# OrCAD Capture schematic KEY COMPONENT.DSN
size A1; title: Index; note: Index
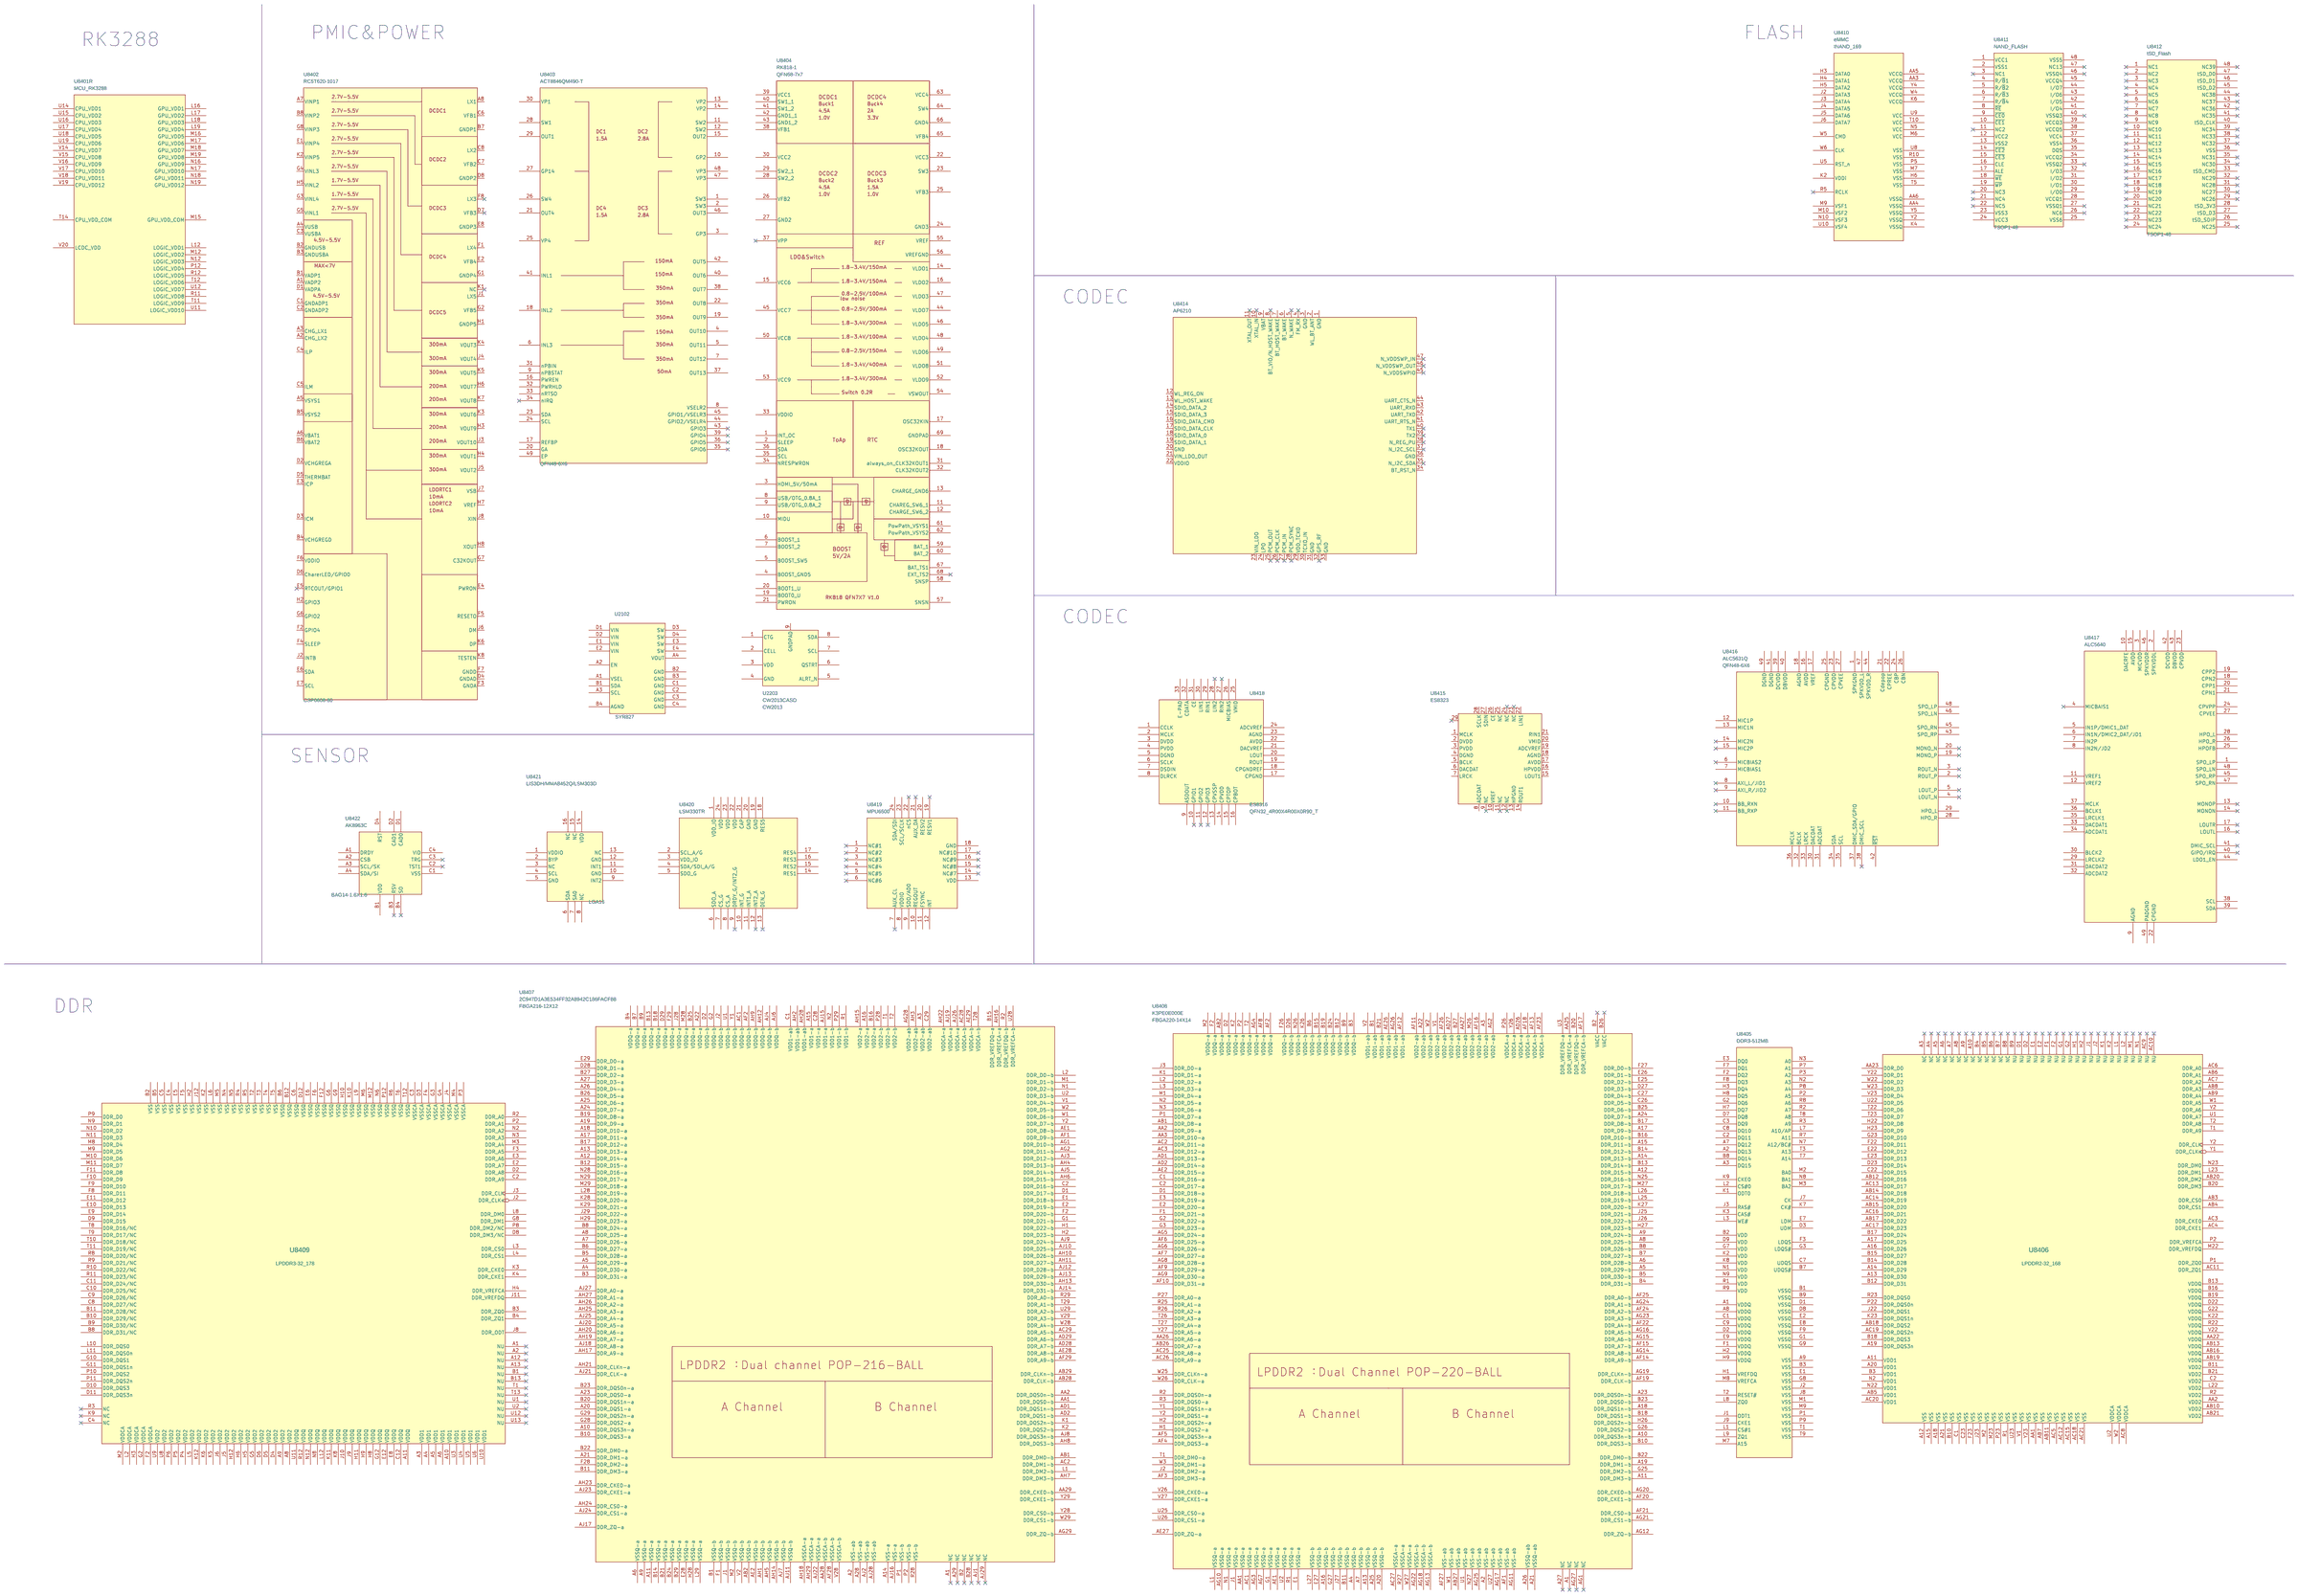
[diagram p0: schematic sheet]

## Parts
U2102  SYR827  [WLCSP-20]
U2203  CW2013CASD  [CW2013]
U8401  MCU_RK3288  [BGA636_19x19]  (section R)
U8402  RC5T620-1017  [CSP0608-80]
U8403  ACT8846QM490-T  [QFN48-6X6]
U8404  RK818-1  [QFN68-7x7]
U8405  DDR3-512MB  [FBGA96-10x14]
U8406  LPDDR2-32_168  [FBGA168-12X12]
U8407  2C947D1A3E534FF32A8942C186FACF88  [FBGA216-12X12]
U8408  K3PE0E000E  [FBGA220-14X14]
U8409  LPDDR3-32_178  [FBGA178-13X11.5]
U8410  eMMC  [INAND_169]
U8411  NAND_FLASH  [TSOP1-48]
U8412  tSD_Flash  [TSOP1-48]
U8414  AP6210  [AP6XXX]
U8415  ES8323  [WM8988]
U8416  ALC5631Q  [QFN48-6X6]
U8417  ALC5640  [763_ALC3224]
U8418  ES8316  [QFN32_4R00X4R00X0R90_T]
U8419  MPU6500  [QFN24_3R00X3R00X0R90]
U8420  LSM330TR  [LGA-24L]
U8421  LIS3DH/MMA8452Q/LSM303D  [LGA16]
U8422  AK8963C  [BAG14-1.6X1.6]

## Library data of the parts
U2102 = BB27_0
U2203 = Gage-CW2013: Fuel Gauge with Low-SOC Alert,2.5V~4.5V,TDFN8,-20 ~70℃
U8401 = MCU_RK3288
U8402 = 5T619_2
U8403 = PMIC_ACT8846: PMU IC
U8404 = PMIC_RK819_0: ROCKCHIP PMIC; Created by: JJJ; Manufacturer: Rockchip (瑞芯微); Manufacturer PN: RK819; Part Type: PMIC; Priority: A; RK PN: RK819
U8405 = DDR3_FBGA96
U8406 = LPDDR2-32_3
U8407 = K3PE0E000E_1
U8408 = K3PE0E000E_0
U8409 = LPDDR3-32bit-178PIN
U8410 = INAND_1: NAND Flash,H26M54001BKR,2.7V,3.3V,3.6V,128G,N/A,-25℃~85℃,FBGA-169P
U8411 = NANDFLASH_0: NAND Flash,2.7V,3.3V,3.6V,2G*8,N/A,-40℃~85℃,TSOP-48P; NAND FLASH: 1
U8412 = TSD_0: NAND Flash,2.7V,3.3V,3.6V,2G*8,N/A,-40℃~85℃,TSOP-48P; NAND FLASH: 1; ROW: 1
U8414 = WIFI-AP6XXX: WIFI&BT; ORCAD_LIB: MODULE; QVL: AMPAK
U8415 = wm8750_1: CODEC; Part_Type: 音频解码IC
U8416 = CODEC-ALC5631Q
U8417 = CODEC-ALC3224: CODEC
U8418 = CODEC_ES8316: Low Power Audio CODEC; Created by: JJJ; Manufacturer: Everest（顺芯）; Part Type: Codec; Priority: A
U8419 = Sensor_MPU6500
U8420 = LSM330
U8421 = MMA8452Q: G_Sensor,LIS3DH/MMA8452Q,1.95V~3.6V,LGA-16,3X3X1.0,-40°C ~ +85°C
U8422 = Sensor-AK8963C

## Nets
AGND: U8416.18(AGND)
AVDD: U8416.16(AVDD)
DGND: U8416.41(DGND) U8416.49(DGND)
GND: U8420.19(GND) U8420.20(GND)
VCC: U8410.M6(VCC) U8410.N5(VCC) U8410.T10(VCC) U8410.U9(VCC)
VCC1: U8411.1(VCC1)
VCC2: U8411.12(VCC2)
VCC3: U8411.24(VCC3)
VCC4: U8411.37(VCC4)
VCCQ: U8410.AA3(VCCQ) U8410.AA5(VCCQ) U8410.K6(VCCQ) U8410.W4(VCCQ) U8410.Y4(VCCQ)
VCCQ2: U8411.34(VCCQ2)
VCCQ3: U8411.39(VCCQ3)
VCCQ5: U8411.38(VCCQ5)
VDD: U8420.22(VDD) U8420.23(VDD) U8420.24(VDD)
VDD1: U8406.A11(VDD1) U8406.A20(VDD1) U8406.AB5(VDD1) U8406.AC20(VDD1) U8406.B3(VDD1) U8406.N2(VDD1) U8406.N22(VDD1) U8409.A3(VDD1) U8409.A4(VDD1) U8409.A5(VDD1) U8409.A6(VDD1) U8409.A10(VDD1) U8409.U3(VDD1) U8409.U4(VDD1) U8409.U5(VDD1) U8409.U6(VDD1) U8409.U10(VDD1)
VDD2: U8406.AA2(VDD2) U8406.AB10(VDD2) U8406.AB21(VDD2) U8406.B11(VDD2) U8406.B21(VDD2) U8406.C2(VDD2) U8406.L22(VDD2) U8406.R2(VDD2) U8409.A8(VDD2) U8409.A9(VDD2) U8409.D4(VDD2) U8409.D5(VDD2) U8409.D6(VDD2) U8409.G5(VDD2) U8409.H5(VDD2) U8409.H6(VDD2) U8409.H12(VDD2) U8409.J5(VDD2) U8409.J6(VDD2) U8409.K5(VDD2) U8409.K6(VDD2) U8409.K12(VDD2) U8409.L5(VDD2) U8409.P4(VDD2) U8409.P5(VDD2) U8409.P6(VDD2) U8409.U8(VDD2) U8409.U9(VDD2)
VDD_IO: U8420.1(VDD_IO) U8420.3(VDD_IO)
VDDCA: U8406.AC8(VDDCA) U8406.U2(VDDCA) U8406.W2(VDDCA) U8409.F2(VDDCA) U8409.G2(VDDCA) U8409.H3(VDDCA) U8409.L2(VDDCA) U8409.M2(VDDCA)
VDDQ: U8406.AA22(VDDQ) U8406.AB13(VDDQ) U8406.AB16(VDDQ) U8406.AB19(VDDQ) U8406.B13(VDDQ) U8406.B16(VDDQ) U8406.B19(VDDQ) U8406.D22(VDDQ) U8406.G22(VDDQ) U8406.K22(VDDQ) U8406.R22(VDDQ) U8406.V22(VDDQ) U8409.A11(VDDQ) U8409.C12(VDDQ) U8409.E8(VDDQ) U8409.E12(VDDQ) U8409.G12(VDDQ) U8409.H8(VDDQ) U8409.H9(VDDQ) U8409.H11(VDDQ) U8409.J9(VDDQ) U8409.J10(VDDQ) U8409.K8(VDDQ) U8409.K11(VDDQ) U8409.L12(VDDQ) U8409.N8(VDDQ) U8409.N12(VDDQ) U8409.R12(VDDQ) U8409.U11(VDDQ)
VSS: U8406.A12(VSS) U8406.A15(VSS) U8406.A18(VSS) U8406.A21(VSS) U8406.AA1(VSS) U8406.AB7(VSS) U8406.AB11(VSS) U8406.AC5(VSS) U8406.AC12(VSS) U8406.AC15(VSS) U8406.AC18(VSS) U8406.AC21(VSS) U8406.B10(VSS) U8406.C1(VSS) U8406.C23(VSS) U8406.F23(VSS) U8406.J23(VSS) U8406.M2(VSS) U8406.M23(VSS) U8406.P23(VSS) U8406.R1(VSS) U8406.U23(VSS) U8406.V1(VSS) U8406.Y23(VSS) U8409.B2(VSS) U8409.B5(VSS) U8409.C5(VSS) U8409.E4(VSS) U8409.E5(VSS) U8409.F5(VSS) U8409.H2(VSS) U8409.J12(VSS) U8409.K2(VSS) U8409.L6(VSS) U8409.M5(VSS) U8409.N4(VSS) U8409.N5(VSS) U8409.R4(VSS) U8409.R5(VSS) U8409.T2(VSS) U8409.T3(VSS) U8409.T4(VSS) U8409.T5(VSS) U8410.H6(VSS) U8410.M7(VSS) U8410.P5(VSS) U8410.R10(VSS) U8410.T5(VSS) U8410.U8(VSS) U8412.36(VSS)
VSS1: U8411.2(VSS1)
VSS2: U8411.13(VSS2)
VSS3: U8411.23(VSS3)
VSS4: U8411.36(VSS4)
VSS5: U8411.48(VSS5)
VSS6: U8411.25(VSS6)
VSSCA: U8409.C3(VSSCA) U8409.D3(VSSCA) U8409.F4(VSSCA) U8409.G3(VSSCA) U8409.G4(VSSCA) U8409.J4(VSSCA) U8409.M4(VSSCA) U8409.P3(VSSCA)
VSSQ: U8409.B6(VSSQ) U8409.B12(VSSQ) U8409.C6(VSSQ) U8409.D12(VSSQ) U8409.E6(VSSQ) U8409.F6(VSSQ) U8409.F12(VSSQ) U8409.G6(VSSQ) U8409.G9(VSSQ) U8409.H10(VSSQ) U8409.K10(VSSQ) U8409.L9(VSSQ) U8409.M6(VSSQ) U8409.M12(VSSQ) U8409.N6(VSSQ) U8409.P12(VSSQ) U8409.R6(VSSQ) U8409.T6(VSSQ) U8409.T12(VSSQ) U8410.AA4(VSSQ) U8410.AA6(VSSQ) U8410.K4(VSSQ) U8410.Y2(VSSQ) U8410.Y5(VSSQ)
CPGND: U8416.25(CPGND)
CPU_VDD1: U8401.U14(CPU_VDD1)
CPU_VDD2: U8401.U15(CPU_VDD2)
CPU_VDD3: U8401.U16(CPU_VDD3)
CPU_VDD4: U8401.U17(CPU_VDD4)
CPU_VDD5: U8401.U18(CPU_VDD5)
CPU_VDD6: U8401.U19(CPU_VDD6)
CPU_VDD7: U8401.V14(CPU_VDD7)
CPU_VDD8: U8401.V15(CPU_VDD8)
CPU_VDD9: U8401.V16(CPU_VDD9)
CPU_VDD10: U8401.V17(CPU_VDD10)
CPU_VDD11: U8401.V18(CPU_VDD11)
CPU_VDD12: U8401.V19(CPU_VDD12)
CPVDD: U8416.23(CPVDD)
DBVDD: U8416.40(DBVDD)
DCVDD: U8416.39(DCVDD)
DDR_VREFDQ: U8406.M22(DDR_VREFDQ) U8409.J11(DDR_VREFDQ)
GPU_VDD1: U8401.L16(GPU_VDD1)
GPU_VDD2: U8401.L17(GPU_VDD2)
GPU_VDD3: U8401.L18(GPU_VDD3)
GPU_VDD4: U8401.L19(GPU_VDD4)
GPU_VDD5: U8401.M16(GPU_VDD5)
GPU_VDD6: U8401.M17(GPU_VDD6)
GPU_VDD7: U8401.M18(GPU_VDD7)
GPU_VDD8: U8401.M19(GPU_VDD8)
GPU_VDD9: U8401.N16(GPU_VDD9)
GPU_VDD10: U8401.N17(GPU_VDD10)
GPU_VDD11: U8401.N18(GPU_VDD11)
GPU_VDD12: U8401.N19(GPU_VDD12)
LCDC_VDD: U8401.V20(LCDC_VDD)
LOGIC_VDD1: U8401.L12(LOGIC_VDD1)
LOGIC_VDD2: U8401.M12(LOGIC_VDD2)
LOGIC_VDD3: U8401.N12(LOGIC_VDD3)
LOGIC_VDD4: U8401.P12(LOGIC_VDD4)
LOGIC_VDD5: U8401.R12(LOGIC_VDD5)
LOGIC_VDD6: U8401.T12(LOGIC_VDD6)
LOGIC_VDD7: U8401.U12(LOGIC_VDD7)
LOGIC_VDD8: U8401.R11(LOGIC_VDD8)
LOGIC_VDD9: U8401.T11(LOGIC_VDD9)
LOGIC_VDD10: U8401.U11(LOGIC_VDD10)

Not connected (* = marked no-connect by the designer): U2102 A1(VSEL) A2(EN) A3(SCL) A4(VOUT) B1(SDA) B2(GND) B3(GND) B4(AGND) C1(GND) C2(GND) C3(GND) C4(GND) D1(VIN) D2(VIN) D3(SW) D4(SW) E1(VIN) E2(VIN) E3(SW) E4(SW); U2203 1(CTG) 2(CELL) 3(VDD) 4(GND) 5(ALRT_N) 6(QSTRT) 7(SCL) 8(SDA) 9(GNDPAD); U8401 M15(GPU_VDD_COM) T14(CPU_VDD_COM); U8402 A1(VADP2) A2(CHG_LX2) A3(CHG_LX1) A4(VUSB) A5(VSYS1) A6(VBAT1) A7(VINP1) A8(LX1) B1(VADP1) B2(GNDUSB) B3(GNDUSBA) B4(VCHGREGD) B5(VSYS2) B6(VBAT2) B7(GNDP1) B8(VINP2) C1(GNDADP1) C2(GNDADP2) C3(VUSBA) C4(ILP) C5(ILM) C6(VFB1) C7(VFB2) C8(LX2) D1(VADPA) D2(VCHGREGA) D3(ICM) D4(GNDAD) D5(THERMBAT) D6(CharerLED/GPIO0) D7(VFB3)* D8(GNDP2) E1(VINP4) E2(VFB4) E3(ICP) E4(PWRON) E5(RTCOUT/GPIO1)* E6(SDA) E7(SCL) E8(GNDP3) F1(LX4) F2(GPIO4) F3(GNDA) F4(SLEEP) F5(RESETO) F6(VDDIO) F7(GNDD) F8(LX3)* G1(GNDP4) G2(VFB5) G3(VINL4) G4(VINL3) G5(VINL1) G6(GPIO2) G7(C32KOUT) G8(VINP3) H1(GNDP5) H2(GPIO3) H3(VOUT9) H4(VOUT1) H5(VINL2) H6(VOUT7) H7(VREF) H8(XOUT) J1(LX5) J2(INTB) J3(VOUT10) J4(VOUT4) J5(VOUT2) J6(DM) J7(VSB) J8(XIN) K1(NC)* K2(VINP5) K3(VOUT6) K4(VOUT3) K5(VOUT5) K6(DP) K7(VOUT8) K8(TESTEN); U8403 1(SW3) 2(SW3) 3(GP3) 4(OUT10) 5(OUT11) 6(INL3) 7(OUT12) 8(VSELR2) 9(nPBSTAT) 10(GP2) 11(SW2) 12(SW2) 13(VP2) 14(VP2) 15(OUT2) 16(PWREN) 17(REFBP) 18(INL2) 19(OUT9) 20(GA) 21(OUT4) 22(OUT8) 23(SDA) 24(SCL) 25(VP4) 26(SW4) 27(GP14) 28(SW1) 29(OUT1) 30(VP1) 31(nPBIN) 32(PWRHLD) 33(nRTSO) 34(nIRQ)* 35(GPIO6)* 36(GPIO5)* 37(OUT13) 38(OUT7) 39(GPIO4)* 40(OUT6) 41(INL1) 42(OUT5) 43(GPIO3)* 44(GPIO2/VSELR4) 45(GPIO1/VSELR3) 46(OUT3) 47(VP3) 48(VP3) 49(EP); U8404 1(INT_OC) 2(SLEEP) 3(HDMI_5V/50mA) 4(BOOST_GND5) 5(BOOST_SW5) 6(BOOST_1) 7(BOOST_2) 8(USB/OTG_0.8A_1) 9(USB/OTG_0.8A_2) 10(MIDU) 11(CHAREG_SW6_1) 12(CHARGE_SW6_2) 13(CHARGE_GND6) 14(VLDO1) 15(VCC6) 16(VLDO2) 17(OSC32KIN) 18(OSC32KOUT) 19(BOOT0_U) 20(BOOT1_U) 21(PWRON) 22(VCC3) 23(SW3) 24(GND3) 25(VFB3) 26(VFB2) 27(GND2) 28(SW2_2) 29(SW2_1) 30(VCC2) 31(always_on_CLK32KOUT1) 32(CLK32KOUT2) 33(VDDIO) 34(NRESPWRON) 35(SCL) 36(SDA) 37(VPP)* 38(VFB1) 39(VCC1) 40(SW1_1) 41(SW1_2) 42(GND1_1) 43(GND1_2) 44(VLDO7) 45(VCC7) 46(VLDO5) 47(VLDO3) 48(VLDO4) 49(VLDO6) 50(VCC8) 51(VLDO8) 52(VLDO9) 53(VCC9) 54(VSWOUT) 55(VREF) 56(VREFGND) 57(SNSN) 58(SNSP) 59(BAT_1) 60(BAT_2) 61(PowPath_VSYS1) 62(PowPath_VSYS2) 63(VCC4) 64(SW4) 65(VFB4) 66(GND4) 67(BAT_TS1) 68(EXT_TS2)* 69(GNDPAD); U8405 A1(VDDQ) A2(DQ13) A3(DQ15) A7(DQ12) A8(VDDQ) A9(VSS) B1(VSSQ) B2(VDD) B3(VSS) B7(UDQS#) B8(DQ14) B9(VSSQ) C1(VDDQ) C2(DQ11) C3(DQ9) C7(UDQS) C8(DQ10) C9(VDDQ) D1(VSSQ) D2(VDDQ) D3(UDM) D7(DQ8) D8(VSSQ) D9(VDD) E1(VSS) E2(VSSQ) E3(DQ0) E7(LDM) E8(VSSQ) E9(VDDQ) F1(VDDQ) F2(DQ2) F3(LDQS) F7(DQ1) F8(DQ3) F9(VSSQ) G1(VSSQ) G2(DQ6) G3(LDQS#) G7(VDD) G8(VSS) G9(VSSQ) H1(VREFDQ) H2(VDDQ) H3(DQ4) H7(DQ7) H8(DQ5) H9(VDDQ) J1(ODT1) J2(VSS) J3(RAS#) J7(CK) J8(VSS) J9(CKE1) K1(ODT0) K2(VDD) K3(CAS#) K7(CK#) K8(VDD) K9(CKE0) L1(CS#1) L2(CS#0) L3(WE#) L7(A10/AP) L8(ZQ0) L9(ZQ1) M1(VSS) M2(BA0) M3(BA2) M7(A15) M8(VREFCA) M9(VSS) N1(VDD) N2(A3) N3(A0) N7(A12/BC#) N8(BA1) N9(VDD) P1(VSS) P2(A5) P3(A2) P7(A1) P8(A4) P9(VSS) R1(VDD) R2(A7) R3(A9) R7(A11) R8(A6) R9(VDD) T1(VSS) T2(RESET#) T3(A13) T7(A14) T8(A8) T9(VSS); U8406 A3(NC)* A4(NC)* A5(NC)* A6(NC)* A7(NC)* A8(NC)* A9(NC)* A10(NC)* A13(DDR_D30) A14(DDR_D29) A16(DDR_D26) A17(DDR_D25) A19(DDR_DQS3n) AA23(DDR_D0) AB3(DDR_CS0) AB4(DDR_CS1) AB6(DDR_A1) AB8(DDR_A3) AB9(DDR_A4) AB12(DDR_D16) AB14(DDR_D18) AB15(DDR_D20) AB17(DDR_D22) AB18(DDR_DQS2) AB20(DDR_DM2) AC3(DDR_CKE0) AC4(DDR_CKE1) AC6(DDR_A0) AC7(DDR_A2) AC9(NU)* AC10(NU)* AC11(DDR_ZQ1) AC13(DDR_D17) AC14(DDR_D19) AC16(DDR_D21) AC17(DDR_D23) AC19(DDR_DQS2n) B4(NC)* B5(NC)* B6(NC)* B7(NC)* B8(NC)* B9(NU)* B12(DDR_D31) B14(DDR_D28) B15(DDR_D27) B17(DDR_D24) B18(DDR_DQS3) B20(DDR_DM3) C22(DDR_D15) D1(NU)* D2(NU)* D23(DDR_D14) E1(NU)* E2(NU)* E22(DDR_D12) E23(DDR_D13) F1(NU)* F2(NU)* F22(DDR_D11) G1(NU)* G2(NU)* G23(DDR_D10) H1(NU)* H2(NU)* H22(DDR_D8) H23(DDR_D9) J1(NU)* J2(NU)* J22(DDR_DQS1) K1(NU)* K2(NU)* K23(DDR_DQS1n) L1(NU)* L2(NU)* L23(DDR_DM1) M1(NU)* N1(NU)* N23(DDR_DM0) P1(DDR_ZQ0) P2(DDR_VREFCA) P22(DDR_DQS0n) R23(DDR_DQS0) T1(DDR_A9) T2(DDR_A8) T22(DDR_D6) T23(DDR_D7) U1(DDR_A7) U22(DDR_D5) V2(DDR_A6) V23(DDR_D4) W1(DDR_A5) W22(DDR_D2) W23(DDR_D3) Y1(DDR_CLKn) Y2(DDR_CLK) Y22(DDR_D1); U8407 A1(NC)* A2(VSS-ab) A3(VDD2-ab) A4(DDR_D30-a) A5(DDR_D29-a) A6(VSSQ-a) A7(DDR_D26-a) A8(DDR_D25-a) A9(VSSQ-a) A10(DDR_DQS3n-a) A11(VSSQ-a) A12(DDR_D14-a) A13(DDR_D13-a) A14(VSS-a) A15(VDD1-a) A16(VDD2-a) A17(DDR_D11-a) A18(DDR_D10-a) A19(DDR_D9-a) A20(DDR_DQS1-a) A21(DDR_DM1-a) A22(VDDQ-a) A23(DDR_DQS0-a) A24(DDR_D7-a) A25(DDR_D6-a) A26(DDR_D4-a) A27(DDR_D3-a) A28(VSS-ab) A29(NC)* AA1(DDR_DQS0-b) AA2(DDR_DQS0n-b) AA28(VSSCA-b) AA29(DDR_CKE0-b) AB1(DDR_DM0-b) AB2(VSSQ-b) AB28(DDR_CLK-b) AB29(DDR_CLKn-b) AC1(VDDQ-b) AC2(DDR_DM1-b) AC28(VDDCA-b) AC29(DDR_A5-b) AD1(DDR_DQS1n-b) AD2(DDR_DQS1-b) AD28(DDR_A7-b) AD29(DDR_A6-b) AE1(DDR_D8-b) AE2(VSSQ-b) AE28(DDR_A8-b) AE29(VDDCA-b) AF1(DDR_D9-b) AF2(VDDQ-b) AF28(VSSCA-b) AF29(DDR_A9-b) AG1(DDR_D10-b) AG2(DDR_D11-b) AG28(VDD2-ab) AG29(DDR_ZQ-b) AH1(VSSQ-b) AH2(VDD1-ab) AH3(VDD2-ab) AH4(DDR_D13-b) AH5(VSSQ-b) AH6(DDR_D15-b) AH7(DDR_DM3-b) AH8(DDR_DQS3-b) AH9(VDDQ-b) AH10(DDR_D26-b) AH11(DDR_D27-b) AH12(VDDQ-b) AH13(DDR_D30-b) AH14(VSSQ-b) AH15(VDD2-a) AH16(DDR_VREFCA-a) AH17(DDR_A9-a) AH18(VSSCA-a) AH19(DDR_A7-a) AH20(DDR_A6-a) AH21(DDR_CLKn-a) AH22(VDDCA-a) AH23(DDR_CKE0-a) AH24(DDR_CS0-a) AH25(DDR_A3-a) AH26(DDR_A2-a) AH27(DDR_A1-a) AH28(VDD1-ab) AH29(VSSCA-a) AJ1(NC)* AJ2(VSS-ab) AJ3(DDR_D12-b) AJ4(VDDQ-b) AJ5(DDR_D14-b) AJ6(VDDQ-b) AJ7(VSSQ-b) AJ8(DDR_DQS3n-b) AJ9(DDR_D24-b) AJ10(DDR_D25-b) AJ11(VSSQ-b) AJ12(DDR_D28-b) AJ13(DDR_D29-b) AJ14(DDR_D31-b) AJ15(VDD1-a) AJ16(VSS-a) AJ17(DDR_ZQ-a) AJ18(DDR_A8-a) AJ19(VDDCA-a) AJ20(DDR_A5-a) AJ21(DDR_CLK-a) AJ22(VSSCA-a) AJ23(DDR_CKE1-a) AJ24(DDR_CS1-a) AJ25(DDR_A4-a) AJ26(VDDCA-a) AJ27(DDR_A0-a) AJ28(VSS-ab) AJ29(NC)* B1(VSSQ-b) B2(NC)* B3(DDR_D31-a) B4(VDDQ-a) B5(DDR_D28-a) B6(DDR_D27-a) B7(VDDQ-a) B8(DDR_D24-a) B9(VDDQ-a) B10(DDR_DQS3-a) B11(DDR_DM3-a) B12(DDR_D15-a) B13(VDDQ-a) B14(VSSQ-a) B15(DDR_VREFDQ-a) B16(VDD2-a) B17(DDR_D12-a) B18(VDDQ-a) B19(DDR_D8-a) B20(DDR_DQS1n-a) B21(VSSQ-a) B22(DDR_DM0-a) B23(DDR_DQS0n-a) B24(VSSQ-a) B25(VDDQ-a) B26(DDR_D5-a) B27(DDR_D2-a) B28(NC)* B29(VSSQ-a) C1(VDD1-ab) C2(DDR_D16-b) C28(VDD1-a) C29(VDD2-ab) D1(DDR_D17-b) D2(VDDQ-b) D28(DDR_D1-a) D29(VDDQ-a) E1(DDR_D18-b) E2(DDR_D19-b) E28(VSSQ-a) E29(DDR_D0-a) F1(VSSQ-b) F2(DDR_D20-b) F28(DDR_DM2-a) F29(VDDQ-a) G1(DDR_D21-b) G2(VDDQ-b) G28(DDR_DQS2-a) G29(DDR_DQS2n-a) H1(DDR_D22-b) H2(DDR_D23-b) H28(VSSQ-a) H29(DDR_D23-a) J1(VSSQ-b) J2(VDDQ-b) J28(VDDQ-a) J29(DDR_D22-a) K1(DDR_DQS2n-b) K2(DDR_DQS2-b) K28(DDR_D20-a) K29(DDR_D21-a) L1(DDR_DM2-b) L2(DDR_D0-b) L28(DDR_D19-a) L29(VSSQ-a) M1(DDR_D1-b) M2(VSSQ-b) M28(VDDQ-a) M29(DDR_D18-a) N1(DDR_D2-b) N2(VDD1-b) N28(DDR_D16-a) N29(DDR_D17-a) P1(VSS-b) P2(VSS-b) P28(VDD2-b) P29(VDD1-b) R1(VDD1-b) R2(DDR_VREFDQ-b) R28(VSS-b) R29(DDR_A0-b) T1(VDD2-b) T2(VDD2-b) T28(VDDCA-b) T29(DDR_A1-b) U1(VDDQ-b) U2(DDR_D3-b) U28(DDR_VREFCA-b) U29(DDR_A2-b) V1(DDR_D4-b) V2(VSSQ-b) V28(VSSCA-b) V29(DDR_A3-b) W1(DDR_D6-b) W2(DDR_D5-b) W28(DDR_A4-b) W29(DDR_CS1-b) Y1(VDDQ-b) Y2(DDR_D7-b) Y28(DDR_CS0-b) Y29(DDR_CKE1-b); U8408 A1(NC)* A2(VSS-ab) A3(VDD2-ab) A4(VSSQ-b) A5(DDR_D29-b) A6(DDR_D28-b) A7(VSSQ-b) A8(DDR_D25-b) A9(DDR_D24-b) A10(DDR_DQS3n-b) A11(DDR_DM3-b) A12(DDR_D15-b) A13(VSSQ-b) A14(DDR_D13-b) A15(DDR_D11-b) A16(VSSQ-b) A17(DDR_D9-b) A18(DDR_DQS1n-b) A19(DDR_DM1-b) A20(VSSQ-b) A21(VSSQ-ab) A22(VDD2-ab) A23(DDR_DQS0n-b) A24(DDR_D7-b) A25(VSSQ-b) A26(VSSQ-ab) A27(NC)* AA1(VSSQ-a) AA2(DDR_D9-a) AA3(DDR_D10-a) AA25(DDR_VREFCA-a) AA26(DDR_A6-a) AA27(VDD2-ab) AB1(DDR_D8-a) AB2(VDDQ-a) AB26(DDR_A7-a) AB27(VSS-ab) AC1(VSSQ-a) AC2(DDR_D11-a) AC3(DDR_D12-a) AC25(DDR_A8-a) AC26(DDR_A9-a) AC27(VSSCA-a) AD1(DDR_D13-a) AD2(DDR_D14-a) AD26(VDDCA-a) AD27(VDD2-ab) AE1(VSSQ-a) AE2(DDR_D15-a) AE26(VDD1-ab) AE27(DDR_ZQ-a) AF1(VSS-ab) AF2(VDDQ-a) AF3(DDR_DM3-a) AF4(DDR_DQS3-a) AF5(DDR_DQS3n-a) AF6(DDR_D25-a) AF7(DDR_D27-a) AF8(VDDQ-a) AF9(DDR_D29-a) AF10(DDR_D31-a) AF11(VDD2-ab) AF12(VDD1-ab) AF13(VDDCA-b) AF14(DDR_A9-b) AF15(DDR_A7-b) AF16(VDD2-ab) AF17(DDR_VREFCA-b) AF18(VDDCA-b) AF19(DDR_CLK-b) AF20(DDR_CKE1-b) AF21(DDR_CS0-b) AF22(DDR_A4-b) AF23(VDDCA-b) AF24(DDR_A2-b) AF25(DDR_A0-b) AF26(VDD2-ab) AF27(VSS-ab) AG1(NC)* AG2(VDD2-ab) AG3(VSSQ-a) AG4(VDDQ-a) AG5(DDR_D24-a) AG6(DDR_D26-a) AG7(VSSQ-a) AG8(DDR_D28-a) AG9(DDR_D30-a) AG10(VSSQ-a) AG11(VSS-ab) AG12(DDR_ZQ-b) AG13(VSSCA-b) AG14(DDR_A8-b) AG15(DDR_A6-b) AG16(DDR_A5-b) AG17(VSS-ab) AG18(VSSCA-b) AG19(DDR_CLKn-b) AG20(DDR_CKE0-b) AG21(DDR_CS1-b) AG22(VSSCA-b) AG23(DDR_A3-b) AG24(DDR_A1-b) AG25(VSS-ab) AG26(VDD1-ab) AG27(NC)* B1(VDD1-ab) B2(VACC)* B3(VDDQ-b) B4(DDR_D31-b) B5(DDR_D30-b) B6(VDDQ-b) B7(DDR_D27-b) B8(DDR_D26-b) B9(VDDQ-b) B10(DDR_DQS3-b) B11(VSSQ-b) B12(VDDQ-b) B13(DDR_D14-b) B14(DDR_D12-b) B15(VDDQ-b) B16(DDR_D10-b) B17(DDR_D8-b) B18(DDR_DQS1-b) B19(VDDQ-b) B20(DDR_VREFDQ-b) B21(VDD1-ab) B22(DDR_DM0-b) B23(DDR_DQS0-b) B24(VDDQ-b) B25(DDR_D6-b) B26(VACC)* B27(VDD2-ab) C1(DDR_D16-a) C2(DDR_D17-a) C26(DDR_D5-b) C27(DDR_D4-b) D1(DDR_D18-a) D2(VDDQ-a) D26(VDDQ-b) D27(DDR_D3-b) E1(VSSQ-a) E2(DDR_D20-a) E3(DDR_D19-a) E25(DDR_D2-b) E26(DDR_D1-b) E27(VSSQ-b) F1(DDR_D21-a) F2(VDDQ-a) F26(VDDQ-b) F27(DDR_D0-b) G1(VSSQ-a) G2(DDR_D22-a) G3(DDR_D23-a) G25(DDR_DM2-b) G26(DDR_DQS2-b) G27(VSSQ-b) H1(DDR_DQS2-a) H2(DDR_DQS2n-a) H26(DDR_DQS2n-b) H27(DDR_D23-b) J1(VSSQ-a) J2(DDR_DM2-a) J3(DDR_D0-a) J25(DDR_D21-b) J26(DDR_D22-b) J27(VSSQ-b) K1(DDR_D1-a) K2(VDDQ-a) K26(VDDQ-b) K27(DDR_D20-b) L1(VSSQ-a) L2(DDR_D2-a) L3(DDR_D3-a) L25(DDR_D19-b) L26(DDR_D18-b) L27(VSSQ-b) M1(DDR_D4-a) M2(VDDQ-a) M26(VDD2-ab) M27(DDR_D17-b) N1(VSSQ-a) N2(DDR_D5-a) N3(DDR_D6-a) N25(DDR_D16-b) N26(VDDQ-b) N27(VSS-ab) P1(DDR_D7-a) P2(VDDQ-a) P26(VDDCA-a) P27(DDR_A0-a) R1(VSSQ-a) R2(DDR_DQS0n-a) R3(DDR_DQS0-a) R25(DDR_A1-a) R26(DDR_A2-a) R27(VSSCA-a) T1(DDR_DM0-a) T2(VDDQ-a) T26(DDR_A3-a) T27(DDR_A4-a) U1(VSS-ab) U2(VSSQ-a) U3(DDR_VREFDQ-a) U25(DDR_CS0-a) U26(DDR_CS1-a) U27(VSS-ab) V1(VDD2-ab) V2(VDD1-ab) V26(DDR_CKE0-a) V27(DDR_CKE1-a) W1(VSS-ab) W2(VDD2-ab) W3(DDR_DM1-a) W25(DDR_CLKn-a) W26(DDR_CLK-a) W27(VSSCA-a) Y1(DDR_DQS1n-a) Y2(DDR_DQS1-a) Y26(VDDCA-a) Y27(DDR_A5-a); U8409 A1(NU)* A2(NU)* A12(NU)* A13(NU)* B1(NU)* B3(DDR_ZQ0) B4(DDR_ZQ1) B8(DDR_D31/NC) B9(DDR_D30/NC) B10(DDR_D29/NC) B11(DDR_D28/NC) B13(NU)* C2(DDR_A9) C4(NC)* C8(DDR_D27/NC) C9(DDR_D26/NC) C10(DDR_D25/NC) C11(DDR_D24/NC) D2(DDR_A8) D8(DDR_DM3/NC) D9(DDR_D15) D10(DDR_DQS3) D11(DDR_DQS3n) E2(DDR_A7) E3(DDR_A6) E9(DDR_D14) E10(DDR_D13) E11(DDR_D12) F3(DDR_A5) F8(DDR_D11) F9(DDR_D10) F10(DDR_D9) F11(DDR_D8) G8(DDR_DM1) G10(DDR_DQS1) G11(DDR_DQS1n) H4(DDR_VREFCA) J2(DDR_CLKn) J3(DDR_CLK) J8(DDR_ODT) K3(DDR_CKE0) K4(DDR_CKE1) K9(NC)* L3(DDR_CS0) L4(DDR_CS1) L8(DDR_DM0) L10(DDR_DQS0) L11(DDR_DQS0n) M3(DDR_A4) M8(DDR_D4) M9(DDR_D5) M10(DDR_D6) M11(DDR_D7) N2(DDR_A2) N3(DDR_A3) N9(DDR_D1) N10(DDR_D2) N11(DDR_D3) P2(DDR_A1) P8(DDR_DM2/NC) P9(DDR_D0) P10(DDR_DQS2) P11(DDR_DQS2n) R2(DDR_A0) R3(NC)* R8(DDR_D20/NC) R9(DDR_D21/NC) R10(DDR_D22/NC) R11(DDR_D23/NC) T1(NU)* T8(DDR_D16/NC) T9(DDR_D17/NC) T10(DDR_D18/NC) T11(DDR_D19/NC) T13(NU)* U1(NU)* U2(NU)* U12(NU)* U13(NU)*; U8410 H3(DATA0) H4(DATA1) H5(DATA2) J2(DATA3) J3(DATA4) J4(DATA5) J5(DATA6) J6(DATA7) K2(VDDi) M9(VSF1) M10(VSF2) N10(VSF3) R5(RCLK)* U5(RST_n) U10(VSF4) W5(CMD) W6(CLK); U8411 3(NC1)* 4(R/~{B}1) 5(R/~{B}2) 6(R/~{B}3) 7(R/~{B}4) 8(~{RE}) 9(~{CE0}) 10(~{CE1}) 11(NC2)* 14(~{CE2}) 15(~{CE3}) 16(CLE) 17(ALE) 18(~{WE}) 19(~{WP}) 20(NC3)* 21(NC4)* 22(NC5)* 26(NC6)* 27(VSSQ1)* 28(VCCQ1) 29(I/O0) 30(I/O1) 31(I/O2) 32(I/O3) 33(VSSQ2)* 35(DQS) 40(VSSQ3)* 41(I/O4) 42(I/O5) 43(I/O6) 44(I/O7) 45(VCCQ4) 46(VSSQ4)* 47(NC13)*; U8412 1(NC1)* 2(NC2)* 3(NC3)* 4(NC4)* 5(NC5)* 6(NC6)* 7(NC7)* 8(NC8)* 9(NC9)* 10(NC10)* 11(NC11)* 12(NC12)* 13(NC13)* 14(NC14)* 15(NC15)* 16(NC16)* 17(NC17)* 18(NC18)* 19(NC19)* 20(NC20)* 21(NC21)* 22(NC22)* 23(NC23)* 24(NC24)* 25(NC25)* 26(tSD_SDIP) 27(tSD_D3) 28(tSD_3V3) 29(NC26)* 30(NC27)* 31(NC28)* 32(NC29)* 33(tSD_CMD) 34(NC30)* 35(NC31)* 37(NC32)* 38(NC33)* 39(NC34)* 40(tSD_CLK) 41(NC35)* 42(NC36)* 43(NC37)* 44(NC38)* 45(tSD_D2) 46(tSD_D1) 47(tSD_D0) 48(NC39)*; U8414 1(GND) 2(WL_BT_ANT) 3(GND) 4(FM_RX)* 5(N_WAKE)* 6(BT_WAKE) 7(BT_HOST_WAKE) 8(BT_VIO/N_HOST_WAKE)* 9(VBAT) 10(XTAL_IN)* 11(XTAL_OUT)* 12(WL_REG_ON) 13(WL_HOST_WAKE) 14(SDIO_DATA_2) 15(SDIO_DATA_3) 16(SDIO_DATA_CMD) 17(SDIO_DATA_CLK) 18(SDIO_DATA_0) 19(SDIO_DATA_1) 20(GND) 21(VIN_LDO_OUT) 22(VDDIO) 23(VIN_LDO) 24(LPO) 25(PCM_OUT)* 26(PCM_CLK)* 27(PCM_IN)* 28(PCM_SYNC)* 29(VDD_TCXO) 30(TCXO_IN) 31(GND) 32(GPS_RF)* 33(GND) 34(BT_RST_N) 35(N_I2C_SDA)* 36(GND) 37(N_I2C_SCL)* 38(N_REG_PU)* 39(TX2)* 40(TX1)* 41(UART_RTS_N) 42(UART_TXD) 43(UART_RXD) 44(UART_CTS_N) 45(N_VDDSWPIO)* 46(N_VDDSWP_OUT)* 47(N_VDDSWP_IN)*; U8415 1(MCLK) 2(DVDD) 3(PVDD) 4(DGND) 5(BCLK) 6(DACDAT) 7(LRCK) 8(ADCDAT) 9(NC)* 10(VREF) 11(NC)* 12(NC)* 13(HPGND) 14(ROUT1) 15(LOUT1) 16(HPVDD) 17(AVDD) 18(AGND) 19(ADCVREF) 20(VMID) 21(RIN1) 22(LIN1) 23(NC)* 24(NC)* 25(NC) 26(CE) 27(SDIN) 28(SCLK) 29*; U8416 1(SPKGND) 2(ROUT_P)* 3(ROUT_N)* 4(LOUT_N)* 5(LOUT_P)* 6(MICBIAS2)* 7(MICBIAS1) 8(AXI_L/JID1)* 9(AXI_R/JID2)* 10(BB_RXN)* 11(BB_RXP)* 12(MIC1P) 13(MIC1N) 14(MIC2N)* 15(MIC2P)* 17(VREF) 19(MONO_P)* 20(MONO_N)* 21(Cdepop) 22(CPREE) 24(CBP) 26(CBN) 27(CPVEE) 28(HPO_R) 29(HPO_L) 30(DACDAT) 31(ADCDAT) 32(BCLK) 33(LRCK) 34(SDA) 35(SCL) 36(MCLK) 37(DMIC_SDA/GPIO) 38(DMIC_SCL)* 42(~{RST}) 43(SPO_RP) 44(SPKVDD_R) 45(SPO_RN) 46(SPO_LN) 47(SPKVDD_L) 48(SPO_LP); U8417 1(SPO_LP) 2(SPKVDDL) 3(MICVDD) 4(MICBAIS1)* 5(IN1P/DMIC1_DAT) 6(IN1N/DMIC2_DAT/JD1) 7(IN2P) 8(IN2N/JD2) 9(AGND) 10(DACRFE) 11(VREF1) 12(VREF2) 13(MONOP)* 14(MONON)* 15(AVDD) 16(LOUTL)* 17(LOUTR)* 18(CPN2) 19(CPP2) 20(CPP1) 21(CPN1) 22(CPGND) 23(CPVDD) 24(CPVPP) 25(HPOFB) 26(HPO_R) 27(CPVEE) 28(HPO_L) 29(LRCLK2) 30(BLCK2) 31(DACDAT2) 32(ADCDAT2) 33(DACDAT1) 34(ADCDAT1) 35(LRCLK1) 36(BCLK1) 37(MCLK) 38(SCL) 39(SDA) 40(GIPO/IRQ)* 41(DMIC_SCL)* 42(DCVDD) 43(DBVDD) 44(LDO1_EN) 45(SPO_RP) 46(SPKVDDR) 47(SPO_RN) 48(SPO_LN) 49(PADGND); U8418 1(CCLK) 2(MCLK) 3(DVDD) 4(PVDD) 5(DGND) 6(SCLK) 7(DSDIN) 8(DLRCK) 9(ASDOUT) 10(GPIO1)* 11(GPIO2)* 12(GPIO3)* 13(CPVSSP) 14(CPVDD) 15(CPTOP) 16(CPBOT) 17(CPGND) 18(CPGNDREF) 19(ROUT) 20(LOUT) 21(DACVREF) 22(AVDD) 23(AGND) 24(ADCVREF) 25(VMID) 26(MICBIAS) 27(RIN2)* 28(LIN2)* 29(RIN1) 30(LIN1) 31(CE) 32(CDATA) 33(E-PAD); U8419 1(NC#1)* 2(NC#2)* 3(NC#3)* 4(NC#4)* 5(NC#5)* 6(NC#6)* 7(AUX_CL)* 8(VDDIO) 9(SDO/AD0) 10(REGOUT) 11(FSYNC) 12(INT) 13(VDD) 14(NC#7)* 15(NC#8)* 16(NC#9)* 17(NC#10)* 18(GND) 19(RESV1)* 20(RESV2) 21(AUX_DA)* 22(nCS)* 23(SCL/SCLK) 24(SDA/SDI); U8420 2(SCL_A/G) 4(SDA/SDI_A/G) 5(SDO_G) 6(SDO_A) 7(CS_G) 8(CS_A) 9(DRDY_G/INT2_G)* 10(INT_G) 11(INT1_A) 12(INT2_A)* 13(DEN_G)* 14(RES1) 15(RES2) 16(RES3) 17(RES4) 18(RES5) 21(CAP); U8421 1(VDDIO) 2(BYP) 3(NC) 4(SCL) 5(GND) 6(SDA) 7(SA0) 8(NC) 9(INT2) 10(GND) 11(INT1) 12(GND) 13(NC) 14(VDD) 15(NC) 16(NC); U8422 A1(DRDY) A2(CSB) A3(SCL/SK) A4(SDA/SI) B1(VDD) B3(RSV)* B4(SO)* C1(VSS) C2(TST1)* C3(TRG)* C4(VID) D1(CAD0) D2(CAD1) D4(RST)

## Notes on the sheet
- RK3288
- PMIC&POWER
- FLASH
- CODEC
- CODEC
- SENSOR
- DDR
